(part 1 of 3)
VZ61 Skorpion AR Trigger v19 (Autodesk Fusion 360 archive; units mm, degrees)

design "VZ61 Skorpion AR Trigger" references "KN20 Base"
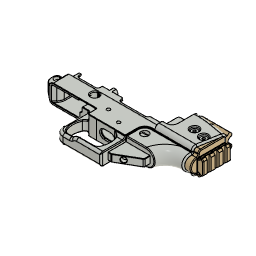
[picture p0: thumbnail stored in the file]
base_feature "Base Feature1"
base_feature "Base Feature1"
base_feature "Base Feature1"
base_feature "Base Feature1"
base_feature "Base Feature1"
base_feature "Base Feature1"
base_feature "Base Feature1"
base_feature "Base Feature1"
base_feature "Base Feature1"
base_feature "Base Feature1"
base_feature "Base Feature1"
base_feature "Base Feature1"
base_feature "Base Feature1"
base_feature "Base Feature1"
base_feature "Base Feature1"
delete_face "DeleteFace1"
sketch "Sketch1" plane through (0, 0, 323.5368) normal (0, 0, 1) x axis (-1, 0, 0)
  line L1 (-298.5983, -1076.3864) -> (-298.5983, -1077.6092)
  line L2 (-296.6171, -1077.6092) -> (-296.6171, -1076.3864)
  line L3 (-258.8669, -1077.8515) -> (-296.6798, -1077.8515)
  line L4 (-258.8669, -1071.9206) -> (-258.8669, -1077.8515)
  line L5 (-257.3965, -1057.333) -> (-257.3965, -1067.8137)
  line L6 (-313.7154, -1057.333) -> (-257.3965, -1057.333)
  line L7 (-315.2154, -1047.0369) -> (-315.2154, -1055.833)
  line L8 (-326.5903, -1045.46) -> (-316.7037, -1045.537)
  line L9 (-363.2907, -1045.46) -> (-326.5903, -1045.46)
  line L10 (-363.7907, -1061.711) -> (-363.7907, -1045.96)
  line L11 (-376.1867, -1071.211) -> (-373.2907, -1071.211)
  line L12 (-376.1867, -1077.8515) -> (-376.1867, -1071.211)
  line L13 (-298.5357, -1077.8515) -> (-376.1867, -1077.8515)
  arc A1 centre (-298.0983, -1077.6092) radius 0.5 clockwise from (-298.5357, -1077.8515) to (-298.5983, -1077.6092)
  arc A2 centre (-299.0983, -1076.3864) radius 0.5 clockwise from (-298.9507, -1075.9087) to (-298.5983, -1076.3864)
  arc A3 centre (-297.6077, -1071.565) radius 4.5466 clockwise from (-298.9507, -1075.9087) to (-296.2648, -1075.9087)
  arc A4 centre (-296.1171, -1076.3864) radius 0.5 clockwise from (-296.6171, -1076.3864) to (-296.2648, -1075.9087)
  arc A5 centre (-297.1171, -1077.6092) radius 0.5 clockwise from (-296.6171, -1077.6092) to (-296.6798, -1077.8515)
  arc A6 centre (-252.3965, -1071.9206) radius 6.4704 clockwise from (-258.8669, -1071.9206) to (-257.3965, -1067.8137)
  arc A7 centre (-313.7154, -1055.833) radius 1.5 clockwise from (-313.7154, -1057.333) to (-315.2154, -1055.833)
  arc A8 centre (-316.7154, -1047.0369) radius 1.5 clockwise from (-316.7037, -1045.537) to (-315.2154, -1047.0369)
  arc A9 centre (-363.2907, -1045.96) radius 0.5 clockwise from (-363.7907, -1045.96) to (-363.2907, -1045.46)
  arc A10 centre (-373.2907, -1061.711) radius 9.5 clockwise from (-363.7907, -1061.711) to (-373.2907, -1071.211)
  circle C1 centre (-323.6435, -1063.6316) radius 2.2185
  circle C2 centre (-345.0557, -1055.656) radius 2.2185
  circle C3 centre (-297.6077, -1071.565) radius 5.125
  concentric A3 C3
  dimension "d1" diameter C3 = 10.25
extrude "Extrude1" cut sketch "Sketch1" profile of L1 A2 A3 A4 L2 C3 against normal blind 23.952
fillet "Fillet1" radius 1
sketch "Sketch2" plane through (0, 0, 312.8688) normal (0, 0, 1) x axis (-1, 0, 0)
  line L1 (-247.0879, -1074.7614) -> (-252.3953, -1074.7614)
  line L2 (-252.3953, -1069.283) -> (-247.0879, -1069.283)
  line L3 (-247.0879, -1075.4614) -> (-252.3953, -1075.4614)
  line L4 (-252.3953, -1068.583) -> (-247.0879, -1068.583)
  line L5 (-252.3965, -1068.583) -> (-247.0879, -1068.583)
  line L6 (-247.0879, -1075.4614) -> (-252.3965, -1075.4614)
  line L7 (-255.8357, -1072.0222) -> (-243.6487, -1072.0222)
  arc A1 centre (-252.3965, -1072.0222) radius 2.7392 clockwise from (-252.3953, -1069.283) to (-252.3953, -1074.7614)
  arc A2 centre (-247.0879, -1072.0222) radius 2.7392 clockwise from (-247.0879, -1069.283) to (-247.0879, -1074.7614)
  arc A3 centre (-252.3965, -1072.0222) radius 2.7392 clockwise from (-252.3965, -1074.7614) to (-252.3965, -1069.283)
  arc A4 centre (-252.3965, -1072.0222) radius 3.4392 clockwise from (-252.3965, -1075.4614) to (-252.3965, -1068.583)
  arc A5 centre (-247.0879, -1072.0222) radius 3.4392 clockwise from (-247.0879, -1068.583) to (-247.0879, -1075.4614)
  circle C1 centre (-252.3965, -1072.0222) radius 3.4392
  arc A6 centre (-252.3965, -1072.0222) radius 3.4392 clockwise from (-252.3965, -1075.4614) to (-252.3965, -1068.583)
  arc A7 centre (-247.0879, -1072.0222) radius 3.4392 clockwise from (-247.0879, -1068.583) to (-247.0879, -1075.4614)
  point P28 (-243.6487, -1072.0222)
  point P29 (-255.8357, -1072.0222)
  point P12 (-252.3965, -1075.4614)
  concentric A3 C1
  tangent L5 A6
  tangent A6 L6
  parallel L5 L6
  tangent L6 A7
  tangent L5 A7
  midpoint A7 P28
  midpoint A6 P29
  midpoint A4 P29
  midpoint A5 P28
  coincident P12 C1
  dimension "d5" = 0.7
  dimension "d6" = 0.7
extrude "Extrude2" cut sketch "Sketch2" profile of A1 L1 A2 L2 A4 L3 A5 L4 C1 along normal blind 7.5
extrude "Extrude3" cut sketch "Sketch2" profile of A1 L1 L2 A4 C1 against normal blind 13
work_plane "WorkPlane1"
fillet "Fillet2" radius 23
fillet "Fillet3" radius 0.5
extrude "Extrude4" cut sketch "Sketch2" profile of L1 A2 L2 A4 L3 A5 L4 C1 L5 A6 L6 A7 along normal blind 12.5
delete_face "DeleteFace2"
delete_face "DeleteFace3"
delete_face "DeleteFace4"
delete_face "DeleteFace5"
delete_face "DeleteFace6"
delete_face "DeleteFace7"
extrude "Extrude5" add of existing geometry blind 0.75
delete_face "DeleteFace8"
delete_face "DeleteFace9"
delete_face "DeleteFace10"
sketch "Sketch3" plane through (0, 0, 323.5368) normal (0, 0, 1) x axis (-1, 0, 0)
  line L1 (-258.8669, -1077.8515) -> (-296.6798, -1077.8515)
  line L2 (-258.8669, -1071.9206) -> (-258.8669, -1077.8515)
  line L3 (-257.3965, -1057.333) -> (-257.3965, -1067.8137)
  line L4 (-313.7154, -1057.333) -> (-257.3965, -1057.333)
  line L5 (-315.2154, -1047.0369) -> (-315.2154, -1055.833)
  line L6 (-326.5903, -1045.46) -> (-316.7037, -1045.537)
  line L7 (-363.2907, -1045.46) -> (-326.5903, -1045.46)
  line L8 (-363.7907, -1061.711) -> (-363.7907, -1045.96)
  line L9 (-376.1867, -1071.211) -> (-373.2907, -1071.211)
  line L10 (-376.1867, -1077.8515) -> (-376.1867, -1071.211)
  line L11 (-298.5357, -1077.8515) -> (-376.1867, -1077.8515)
  circle C1 centre (-345.0557, -1055.656) radius 2
  arc A1 centre (-297.6077, -1071.565) radius 6.125 clockwise from (-298.5983, -1077.6093) to (-296.6171, -1077.6093)
  arc A2 centre (-297.1171, -1077.6092) radius 0.5 clockwise from (-296.6171, -1077.6093) to (-296.6798, -1077.8515)
  arc A3 centre (-252.3965, -1071.9206) radius 6.4704 clockwise from (-258.8669, -1071.9206) to (-257.3965, -1067.8137)
  arc A4 centre (-313.7154, -1055.833) radius 1.5 clockwise from (-313.7154, -1057.333) to (-315.2154, -1055.833)
  arc A5 centre (-316.7154, -1047.0369) radius 1.5 clockwise from (-316.7037, -1045.537) to (-315.2154, -1047.0369)
  arc A6 centre (-363.2907, -1045.96) radius 0.5 clockwise from (-363.7907, -1045.96) to (-363.2907, -1045.46)
  arc A7 centre (-373.2907, -1061.711) radius 9.5 clockwise from (-363.7907, -1061.711) to (-373.2907, -1071.211)
  arc A8 centre (-298.0983, -1077.6092) radius 0.5 clockwise from (-298.5357, -1077.8515) to (-298.5983, -1077.6093)
  circle C2 centre (-323.6435, -1063.6316) radius 2
  circle C3 centre (-345.0557, -1055.656) radius 2.175
  circle C4 centre (-323.6435, -1063.6316) radius 2.175
  concentric C1 C3
  concentric C2 C4
  dimension "d17" diameter C3 = 4.35
  dimension "d18" diameter C4 = 4.35
extrude "Extrude6" cut sketch "Sketch3" profile of C1 C2 C3 C4 against normal blind 51
delete_face "DeleteFace11"
sketch "Sketch4" plane through (201.4676, -35.5242, 0) normal (0.9848, -0.1736, 0) x axis (0.1736, 0.9848, 0)
  circle C1 centre (1146.6543, 311.0803) radius 13
  circle C2 centre (1146.6543, 311.0803) radius 13.75
  dimension "d21" = 0.75
extrude "Extrude7" cut sketch "Sketch4" along normal blind 80
fillet "Fillet4" radius 1 1
sketch "Sketch5" plane through (0, 0, 323.5368) normal (0, 0, 1) x axis (-1, 0, 0)
  line L1 (-258.8669, -1077.8515) -> (-296.6798, -1077.8515)
  line L2 (-258.8669, -1071.9206) -> (-258.8669, -1077.8515)
  line L3 (-257.3965, -1057.333) -> (-257.3965, -1067.8137)
  line L4 (-313.7154, -1057.333) -> (-257.3965, -1057.333)
  line L5 (-315.2154, -1047.0369) -> (-315.2154, -1055.833)
  line L6 (-326.5903, -1045.46) -> (-316.7037, -1045.537)
  line L7 (-363.2907, -1045.46) -> (-326.5903, -1045.46)
  line L8 (-363.7907, -1061.711) -> (-363.7907, -1045.96)
  line L9 (-376.1867, -1071.211) -> (-373.2907, -1071.211)
  line L10 (-376.1867, -1077.8515) -> (-376.1867, -1071.211)
  line L11 (-298.5357, -1077.8515) -> (-376.1867, -1077.8515)
  circle C1 centre (-345.0557, -1055.656) radius 2.175
  circle C2 centre (-323.6435, -1063.6316) radius 2.175
  arc A1 centre (-297.6077, -1071.565) radius 6.125 clockwise from (-298.5983, -1077.6093) to (-296.6171, -1077.6093)
  arc A2 centre (-297.1171, -1077.6092) radius 0.5 clockwise from (-296.6171, -1077.6093) to (-296.6798, -1077.8515)
  arc A3 centre (-252.3965, -1071.9206) radius 6.4704 clockwise from (-258.8669, -1071.9206) to (-257.3965, -1067.8137)
  arc A4 centre (-313.7154, -1055.833) radius 1.5 clockwise from (-313.7154, -1057.333) to (-315.2154, -1055.833)
  arc A5 centre (-316.7154, -1047.0369) radius 1.5 clockwise from (-316.7037, -1045.537) to (-315.2154, -1047.0369)
  arc A6 centre (-363.2907, -1045.96) radius 0.5 clockwise from (-363.7907, -1045.96) to (-363.2907, -1045.46)
  arc A7 centre (-373.2907, -1061.711) radius 9.5 clockwise from (-363.7907, -1061.711) to (-373.2907, -1071.211)
  arc A8 centre (-298.0983, -1077.6092) radius 0.5 clockwise from (-298.5357, -1077.8515) to (-298.5983, -1077.6093)
  circle C3 centre (-345.0557, -1055.656) radius 5
  circle C4 centre (-323.6435, -1063.6316) radius 5
  concentric C1 C3
  concentric C2 C4
  dimension "d26" diameter C3 = 10
  dimension "d27" diameter C4 = 10
extrude "Extrude8" add sketch "Sketch5" profile of C1 C2 C3 C4 along normal blind 2
extrude "Extrude9" add sketch "Sketch5" profile of C1 C2 C3 C4 blind -2 from offset -24.913
fillet "Fillet5" radius 1
external_derived "ExternalDerived1"
ground "Ground1"
align "Align1"
extrude "Extrude1" cut of existing geometry blind -1.5
align "Align2"
extrude "Extrude2" cut of existing geometry blind -128.829
extrude "Extrude3" add of existing geometry blind 8
split "Split1" bodies "Picatinny Base (1)", "Picatinny Base (2)", "Picatinny Base (3)"
sketch "Sketch6" plane through (427.1656, 0, 0) normal (1, 0, 0) x axis (0, 1, 0)
  line L1 (1110.3464, 303.2444) -> (1110.3464, 318.9162)
  line L2 (1116.316, 303.2444) -> (1110.3464, 303.2444)
  line L3 (1119.2278, 300.4758) -> (1116.316, 303.2444)
  line L4 (1122.1477, 303.2444) -> (1119.2278, 300.4758)
  line L5 (1122.1477, 318.9162) -> (1122.1477, 303.2444)
  line L6 (1119.2585, 321.6848) -> (1122.1477, 318.9162)
  line L7 (1116.3613, 318.9162) -> (1119.2585, 321.6848)
  line L8 (1110.3464, 318.9162) -> (1116.3613, 318.9162)
  circle C1 centre (1122.1477, 311.0803) radius 5
  point P10 (1122.1477, 311.0803)
  midpoint L5 P10
  dimension "d40" diameter C1 = 10
extrude "Extrude4" cut sketch "Sketch6" profile of L5 C1 against normal blind 50
copy_paste_bodies "CutPasteBodies1"
sketch "Sketch7" plane through (0, 1046.071, 0) normal (0, -1, 0) x axis (1, 0, 0)
  curve K1 (390.5086, 301.0303) -> (390.5086, 321.1303)
  line L1 (364.7827, 321.1303) -> (390.5086, 321.1303)
  curve K2 (364.7827, 321.1303) -> (364.7907, 320.7332)
  line L2 (364.7907, 315.8553) -> (364.7907, 320.7332)
  line L3 (395.5407, 315.8553) -> (364.7907, 315.8553)
  line L4 (396.0407, 315.3553) -> (395.5407, 315.8553)
  line L5 (396.0407, 306.8053) -> (396.0407, 315.3553)
  line L6 (395.5407, 306.3053) -> (396.0407, 306.8053)
  line L7 (364.7907, 306.3053) -> (395.5407, 306.3053)
  line L8 (364.7907, 301.4275) -> (364.7907, 306.3053)
  curve K3 (364.7907, 301.4275) -> (364.7827, 301.0303)
  line L9 (390.5086, 301.0303) -> (364.7827, 301.0303)
  circle C1 centre (373.6312, 303.5803) radius 1.54
  circle C2 centre (373.6312, 303.5803) radius 2
  concentric C1 C2
  dimension "d43" diameter C2 = 4
extrude "Extrude10" cut sketch "Sketch7" profile of C1 C2 against normal blind 14.5
copy_paste "CopyPaste1"
work_plane "WorkPlane2" AlongDistance 0
split "Split1" bodies "AR-15 Buffer Tube"
derived_base_feature "Derived Base Feature2" bodies "Picatinny Base (1)"
work_plane "WorkPlane1" RotateAngle 90
sketch "Sketch1" plane through (29, 0, -19) normal (0.9848, 0, -0.1736) x axis (0, -1, 0)
  line L1 (-15.7419, -31.5631) -> (-15.7419, -2.9544)
  line L2 (-11.5035, -34.8481) -> (-12.4569, -34.8481)
  curve K1 (-11.5035, -34.8481) -> (-9.0091, -37.1129)
  curve K2 (-9.0091, -37.1129) -> (9.0091, -37.1129)
  curve K3 (9.0091, -37.1129) -> (11.5035, -34.8481)
  line L3 (12.4569, -34.8481) -> (11.5035, -34.8481)
  line L4 (15.7419, -2.9544) -> (15.7419, -31.5631)
  line L5 (-12.7419, 0) -> (12.7419, 0)
  closed curve K4 centre (-12.7419, -2.9544)
  arc A1 centre (-12.4569, -31.5631) radius 3.285 clockwise from (-12.4569, -34.8481) to (-15.7419, -31.5631)
  arc A2 centre (12.4569, -31.5631) radius 3.285 clockwise from (15.7419, -31.5631) to (12.4569, -34.8481)
  closed curve K5 centre (12.7419, -2.9544)
  closed curve K6 centre (0, -18.7113)
extrude "Extrude1" add sketch "Sketch1" along a picked direction blind -13
split "Split2"
copy_paste_bodies "CutPasteBodies1"
align "Align1"
extrude "Extrude2" cut of existing geometry blind -1.5
align "Align2"
extrude "Extrude3" cut of existing geometry blind -128.829
component_from_bodies "Body->Comp1"
copy_paste "CopyPaste1"
position "Position1"
extrude "Extrude1" add of existing geometry blind 3
split "Split1" bodies "90 (1)", "90 (2)"
fillet "Fillet1" radius 1
copy_paste_bodies "CopyPasteBodies1"
copy_paste_bodies "CutPasteBodies2"
extrude "Extrude4" cut of existing geometry blind 12.5
split "Split3" bodies "Angled Plate"
sketch "Sketch2" plane through (29, 0, 0) normal (1, 0, 0) x axis (0, 1, 0)
  line L1 (15.7419, 13.05) -> (15.7419, -16)
  line L2 (11.5035, 16.3857) -> (12.4569, 16.3857)
  curve K1 (11.5035, 16.3857) -> (9.0091, 18.6855)
  curve K2 (9.0091, 18.6855) -> (-9.0091, 18.6855)
  curve K3 (-9.0091, 18.6855) -> (-11.5035, 16.3857)
  line L3 (-12.4569, 16.3857) -> (-11.5035, 16.3857)
  line L4 (-15.7419, -16) -> (-15.7419, 13.05)
  line L5 (12.7419, -19) -> (-12.7419, -19)
  arc A1 centre (12.7419, -16) radius 3 clockwise from (15.7419, -16) to (12.7419, -19)
  closed curve K4 centre (12.4569, 13.05)
  closed curve K5 centre (-12.4569, 13.05)
  arc A2 centre (-12.7419, -16) radius 3 clockwise from (-12.7419, -19) to (-15.7419, -16)
  circle C1 centre (0, 0) radius 14.75
extrude "Extrude5" add sketch "Sketch2" along a picked direction blind 2
derived_base_feature "Derived Base Feature3" bodies "Picatinny Base (2)", "Picatinny Base (1)"
copy_paste_bodies "CutPasteBodies3"
align "Align3"
extrude "Extrude6" cut of existing geometry blind -128.829
extrude "Extrude7" cut of existing geometry blind -1.5
align "Align4"
split "Split4" bodies "Non-Angled"
copy_paste_bodies "CutPasteBodies1"
combine "Combine1" bodies "Picatinny Base (1) (1)"
component_from_bodies "Body->Comp2"
copy_paste "CutPaste"
copy_paste_bodies "CopyPasteBodies1"
combine "Combine1"
delete_face "DeleteFace1"
extrude "Extrude11" cut of existing geometry blind -68
fillet "Fillet1" radius 1
fillet "Fillet2" radius 0.5
fillet "Fillet1" radius 1
fillet "Fillet2" radius 1
sketch "Sketch3" plane through (29, 0, 0) normal (-1, 0, 0) x axis (0, -1, 0)
  line L1 (11.5035, 16.3857) -> (12.4569, 16.3857)
  curve K1 (9.0091, 18.6855) -> (11.5035, 16.3857)
  curve K2 (-9.0091, 18.6855) -> (9.0091, 18.6855)
  curve K3 (-11.5035, 16.3857) -> (-9.0091, 18.6855)
  line L2 (-12.4569, 16.3857) -> (-11.5035, 16.3857)
  line L3 (-15.7419, -16) -> (-15.7419, 13.05)
  line L4 (12.7419, -19) -> (-12.7419, -19)
  line L5 (15.7419, 13.05) -> (15.7419, -16)
  closed curve K4 centre (-12.4569, 13.05)
  arc A1 centre (-12.7419, -16) radius 3 clockwise from (-12.7419, -19) to (-15.7419, -16)
  arc A2 centre (12.7419, -16) radius 3 clockwise from (15.7419, -16) to (12.7419, -19)
  closed curve K5 centre (12.4569, 13.05)
  circle C1 centre (0, 0) radius 13.5
extrude "Extrude9" cut sketch "Sketch3" along a picked direction blind 95
delete_face "DeleteFace1"
delete_face "DeleteFace2"
delete_face "DeleteFace3"
delete_face "DeleteFace4"
chamfer "Chamfer1" distance 1.5
chamfer "Chamfer2" distance 1.5
component_from_bodies "Body->Comp3"
offset_faces "OffsetFaces1" distance 0.25
delete_face "DeleteFace12"
sketch "Sketch8" plane through (0, 0, 317.0598) normal (0, 0, 1) x axis (-1, 0, 0)
  line L1 (-247.0879, -1068.583) -> (-252.3953, -1068.583)
  line L2 (-252.3953, -1075.4614) -> (-247.0879, -1075.4614)
  line L3 (-256.8669, -1076.0942) -> (-256.8669, -1071.9206)
  line L4 (-247.6213, -1076.0942) -> (-256.8669, -1076.0942)
  line L5 (-243.5493, -1068.9541) -> (-243.5493, -1072.0222)
  line L6 (-250.416, -1058.9901) -> (-247.2509, -1061.4289)
  line L7 (-250.416, -1067.9128) -> (-250.416, -1058.9901)
  line L8 (-252.3965, -1067.4502) -> (-252.3965, -1071.9206)
  line L9 (-244, -1067.4502) -> (-252.3965, -1067.4502)
  line L10 (-244, -1070.5078) -> (-244, -1067.4502)
  line L11 (-256.8669, -1068.8387) -> (-256.8669, -1071.9206)
  line L12 (-246.0217, -1070.9571) -> (-254.8888, -1070.8604)
  line L13 (-254.8452, -1066.8606) -> (-245.9781, -1066.9573)
  line L14 (-244, -1068.979) -> (-256.8669, -1068.8387)
  arc A1 centre (-247.0879, -1072.0222) radius 3.4392 clockwise from (-247.0879, -1068.583) to (-247.0879, -1075.4614)
  arc A2 centre (-252.3965, -1072.0222) radius 3.4392 clockwise from (-252.3953, -1075.4614) to (-252.3953, -1068.583)
  arc A3 centre (-252.3965, -1071.9206) radius 4.4704 clockwise from (-256.8669, -1071.9206) to (-250.416, -1067.9128)
  arc A4 centre (-247.6213, -1072.0222) radius 4.072 clockwise from (-243.5493, -1072.0222) to (-247.6213, -1076.0942)
  arc A5 centre (-253.0493, -1068.9541) radius 9.5 clockwise from (-247.2509, -1061.4289) to (-243.5493, -1068.9541)
  circle C1 centre (-252.3965, -1071.9206) radius 4.4704
  arc A6 centre (-245.9999, -1068.9572) radius 2 clockwise from (-245.9781, -1066.9573) to (-246.0217, -1070.9571)
  arc A7 centre (-254.867, -1068.8605) radius 2 clockwise from (-254.8888, -1070.8604) to (-254.8452, -1066.8606)
  point P10 (-252.3965, -1071.9206)
  point P20 (-252.3965, -1071.9206)
  point P21 (-252.3965, -1067.4502)
  point P23 (-244, -1070.5078)
  point P9 (-256.8669, -1071.9206)
  point P24 (-256.8669, -1071.9206)
  point P25 (-256.8669, -1068.8387)
  point P32 (-244, -1068.979)
  concentric A3 C1
  vertical L8
  coincident P10 P20
  coincident A3 P21
  coincident C1 P21
  tangent A3 L9
  coincident A1 P23
  perpendicular L9 L10
  coincident P9 P24
  tangent A3 L11
  tangent L12 A6
  tangent A6 L13
  parallel L12 L13
  tangent L13 A7
  tangent L12 A7
  midpoint P25 A7
  midpoint A6 P32
  midpoint L10 P32
  dimension "d81" diameter A6 = 4
extrude "Extrude12" cut sketch "Sketch8" profile of A3 L7 C1 L9 L11 L13 A7 along normal blind 42
extrude "Extrude13" cut of existing geometry blind -15 from offset -11.959
sketch "Sketch9" plane through (0, 0, 305.1008) normal (0, 0, -1) x axis (1, 0, 0)
  line L1 (250.416, -1058.9901) -> (250.416, -1066.9089)
  line L2 (247.2509, -1061.4289) -> (250.416, -1058.9901)
  line L3 (243.5493, -1072.0222) -> (243.5493, -1068.9541)
  line L4 (256.8669, -1076.0942) -> (247.6213, -1076.0942)
  line L5 (256.8669, -1071.9206) -> (256.8669, -1076.0942)
  line L6 (256.8669, -1068.8387) -> (256.8669, -1071.9206)
  line L7 (250.416, -1066.9089) -> (254.8452, -1066.8606)
  line L8 (252.3965, -1071.0222) -> (252.3965, -1072.0222)
  arc A1 centre (253.0493, -1068.9541) radius 9.5 clockwise from (243.5493, -1068.9541) to (247.2509, -1061.4289)
  arc A2 centre (247.6213, -1072.0222) radius 4.072 clockwise from (247.6213, -1076.0942) to (243.5493, -1072.0222)
  arc A3 centre (254.867, -1068.8605) radius 2 clockwise from (254.8452, -1066.8606) to (256.8669, -1068.8387)
  arc A4 centre (252.3965, -1072.0222) radius 3.4392 clockwise from (252.3953, -1075.4614) to (252.3953, -1068.583)
  arc A5 centre (252.3965, -1072.0222) radius 3.4392 clockwise from (252.3953, -1068.583) to (252.3953, -1075.4614)
  circle C1 centre (252.3965, -1071.0222) radius 3.375
  point P17 (252.3965, -1072.0222)
  point P18 (252.3965, -1072.0222)
  point P19 (252.3965, -1071.0222)
  point P20 (252.3965, -1071.0222)
  coincident P17 P18
  vertical L8
  coincident P19 P20
  dimension "d85" distance P18 P19 = 1
  dimension "d86" diameter C1 = 6.75
extrude "Extrude14" cut sketch "Sketch9" profile of A4 A5 C1 against normal blind 11.959
extrude "Extrude15" add sketch "Sketch9" profile of A4 A5 C1 against normal blind 11.959
delete_face "DeleteFace13"
extrude "Extrude16" cut sketch "Sketch9" profile of A4 A5 C1 against normal blind 33
delete_face "DeleteFace14"
sketch "Sketch10" plane through (0, 0, 317.0598) normal (0, 0, 1) x axis (-1, 0, 0)
  line L1 (-256.8669, -1076.0942) -> (-256.8669, -1068.8387)
  line L2 (-247.6213, -1076.0942) -> (-256.8669, -1076.0942)
  line L3 (-243.5493, -1068.9541) -> (-243.5493, -1072.0222)
  line L4 (-250.416, -1058.9901) -> (-247.2509, -1061.4289)
  line L5 (-250.416, -1066.9089) -> (-250.416, -1058.9901)
  line L6 (-254.8452, -1066.8606) -> (-250.416, -1066.9089)
  line L7 (-255.7715, -1071.0222) -> (-252.3965, -1071.0222)
  line L8 (-249.1465, -1074.3972) -> (-252.3965, -1074.3972)
  line L9 (-252.3965, -1067.6472) -> (-249.1465, -1067.6472)
  line L10 (-245.7715, -1071.0222) -> (-255.7715, -1071.0222)
  arc A1 centre (-247.6213, -1072.0222) radius 4.072 clockwise from (-243.5493, -1072.0222) to (-247.6213, -1076.0942)
  arc A2 centre (-253.0493, -1068.9541) radius 9.5 clockwise from (-247.2509, -1061.4289) to (-243.5493, -1068.9541)
  arc A3 centre (-254.867, -1068.8605) radius 2 clockwise from (-256.8669, -1068.8387) to (-254.8452, -1066.8606)
  circle C1 centre (-252.3965, -1071.0222) radius 3.375
  arc A4 centre (-249.1465, -1071.0222) radius 3.375 clockwise from (-249.1465, -1067.6472) to (-249.1465, -1074.3972)
  arc A5 centre (-252.3965, -1071.0222) radius 3.375 clockwise from (-252.3965, -1074.3972) to (-252.3965, -1067.6472)
  circle C2 centre (-252.3965, -1071.0222) radius 3.375
  point P14 (-252.3965, -1071.0222)
  point P15 (-252.3965, -1071.0222)
  point P16 (-255.7715, -1071.0222)
  point P23 (-245.7715, -1071.0222)
  coincident P14 P15
  coincident C1 P16
  horizontal L7
  tangent L8 A4
  tangent A4 L9
  parallel L8 L9
  tangent L9 A5
  tangent L8 A5
  midpoint P16 A5
  midpoint A4 P23
  parallel L7 L10
  tangent L9 C2
  dimension "d93" distance P16 P23 = 10
fillet "Fillet6" radius 2.5
delete_face "DeleteFace15"
sketch "Sketch11" plane through (0, 0, 317.0598) normal (0, 0, 1) x axis (-1, 0, 0)
  line L1 (-256.8669, -1076.0942) -> (-256.8669, -1068.8387)
  line L2 (-247.6213, -1076.0942) -> (-256.8669, -1076.0942)
  line L3 (-243.5493, -1068.9541) -> (-243.5493, -1072.0222)
  line L4 (-250.416, -1058.9901) -> (-247.2509, -1061.4289)
  line L5 (-250.416, -1064.4088) -> (-250.416, -1058.9901)
  curve K1 (-254.4744, -1066.8647) -> (-250.416, -1064.4088)
  line L6 (-254.8452, -1066.8606) -> (-254.4744, -1066.8647)
  line L7 (-248.4133, -1074.664) -> (-252.1296, -1074.664)
  line L8 (-252.1296, -1067.3803) -> (-248.4133, -1067.3803)
  line L9 (-244.7715, -1071.0222) -> (-255.7715, -1071.0222)
  arc A1 centre (-247.6213, -1072.0222) radius 4.072 clockwise from (-243.5493, -1072.0222) to (-247.6213, -1076.0942)
  arc A2 centre (-253.0493, -1068.9541) radius 9.5 clockwise from (-247.2509, -1061.4289) to (-243.5493, -1068.9541)
  arc A3 centre (-254.867, -1068.8605) radius 2 clockwise from (-256.8669, -1068.8387) to (-254.8452, -1066.8606)
  circle C1 centre (-252.3965, -1071.0222) radius 3.375
  arc A4 centre (-248.4133, -1071.0222) radius 3.6418 clockwise from (-248.4133, -1067.3803) to (-248.4133, -1074.664)
  arc A5 centre (-252.1296, -1071.0222) radius 3.6418 clockwise from (-252.1296, -1074.664) to (-252.1296, -1067.3803)
  point P22 (-255.7715, -1071.0222)
  point P23 (-244.7715, -1071.0222)
  tangent L7 A4
  tangent A4 L8
  parallel L7 L8
  tangent L8 A5
  tangent L7 A5
  midpoint A5 P22
  midpoint A4 P23
  horizontal L9
  coincident C1 P22
  dimension "d95" distance P22 P23 = 11
extrude "Extrude17" cut sketch "Sketch11" profile of C1 L7 A4 L8 A5 against normal blind 4.5
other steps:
derived_base_feature "Derived Base Feature1" bodies "Picatinny Base"
base_feature "Base Feature1" bodies "90"
base_feature "Base Feature1" bodies "Picatinny Base (1) (1)", "Non-Angled"
base_feature "Base Feature1" bodies "Angled Plate"
base_feature "Base Feature1" bodies "AR-15 Buffer Tube"
base_feature "Base Feature2" bodies "Angled Plate (1)"
base_feature "Base Feature2" bodies "Picatinny Base (1)", "90"
base_feature "Base Feature3" bodies "Nub"
base_feature "Base Feature4" bodies "Picatinny Base (1) (1)"
base_feature "Base Feature1"
extrude "Extrude8" cut of existing geometry blind -68
base_feature "Base Feature2" bodies "Picatinny Base (1)"
create_component "CreateComponent1"
create_component "CreateComponent2"
create_component "CreateComponent1"
create_component "CreateComponent1"
create_component "CreateComponent1"
create_component "CreateComponent1"
create_component "CreateComponent2"
create_component "CreateComponent3"
create_component "CreateComponent4"
create_component "CreateComponent2"
create_component "CreateComponent1"
create_component "CreateComponent2"
create_component "CreateComponent3"
create_component "CreateComponent4"
create_component "CreateComponent5"
create_component "CreateComponent3"
create_component "CreateComponent1"
create_component "CreateComponent2"
create_component "CreateComponent3"
create_component "CreateComponent3"
create_component "CreateComponent4"
remove_body "RemoveBody1"
remove_body "RemoveBody2"
create_component "CreateComponent1"
remove_body "RemoveBody1"
remove_body "RemoveBody3"
remove_body "RemoveBody4"
create_component "CreateComponent2"
remove_body "RemoveBody2"
remove_body "RemoveBody3"
create_component "CreateComponent3"
remove_body "RemoveBody4"
remove_instance "RemoveInstance1"
remove_body "RemoveBody1"
create_component "CreateComponent4"
remove_body "RemoveBody5"
named bodies: "Picatinny Base", "Picatinny Base (1)", "Picatinny Base (2)", "Picatinny Base (3)", "AR-15 Buffer Tube", "90", "90 (1)", "90 (2)", "Nub", "Angled Plate", "Picatinny Base (1) (1)", "Non-Angled", "Angled Plate (1)"

design "HRR Blast Shield"
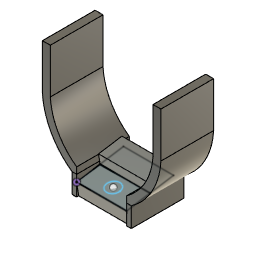
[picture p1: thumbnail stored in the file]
work_plane "WorkPlane1" RotateAngle 9
sketch "Base" plane through (12.125, 0, 0) normal (0, -0.1564, 0.9877) x axis (1, 0, 0)
  line L1 (19, 0) -> (0, 0)
  line L2 (19, 9) -> (19, 0)
  line L3 (0, 9) -> (19, 9)
  line L4 (0, 0) -> (0, 9)
  line L5 (19, 9) -> (0, 9)
  line L6 (19, 18) -> (19, 9)
  line L7 (0, 18) -> (19, 18)
  line L8 (0, 9) -> (0, 18)
  circle C1 centre (9.4705, 4.5) radius 2.5
  point P1 (0, 0)
  point P2 (0, 0)
  point P3 (19, 0)
  point P5 (0, 9)
  point P7 (19, 9)
  point P9 (0, 18)
  horizontal L1
  vertical L2
  horizontal L3
  vertical L4
  coincident P1 P2
  horizontal L5
  vertical L6
  horizontal L7
  vertical L8
  dimension "d2" distance P2 P3 = 19
  dimension "d3" distance P2 P5 = 9
  dimension "d4" diameter C1 = 5
  dimension "d5" distance P5 P7 = 19
  dimension "d6" distance P5 P9 = 9
extrude "Extrude1" new body sketch "Base" against normal blind 5
extrude "Extrude2" add sketch "Base" profile of L3 L5 L6 L7 L8 along normal blind 3.75
work_plane "WorkPlane2" AlongDistance 5.3
sketch "Blast Shield" plane through (0, 0, 0) normal (0, 1, 0) x axis (1, 0, 0)
  line L1 (2.125, -40) -> (2.125, -23)
  line L2 (-0.875, -40) -> (-0.875, -22.9143)
  line L3 (2.125, -40) -> (-0.875, -40)
  line L4 (12.125, -2.5505) -> (10.3929, -2.5505)
  line L5 (12.125, -5) -> (12.125, -2.5505)
  line L6 (12.125, -5.1117) -> (12.125, -1.4079)
  line L7 (21.625, -5.1117) -> (21.625, -23.1117)
  line L8 (31.125, -5.1117) -> (12.125, -5.1117)
  line L9 (44.125, -40) -> (44.125, -22.9143)
  line L10 (31.125, -5) -> (31.125, -2.5505)
  line L11 (41.125, -40) -> (41.125, -23)
  line L12 (31.125, -2.5505) -> (32.8571, -2.5505)
  line L13 (41.125, -40) -> (44.125, -40)
  circle C1 centre (21.625, -23.1117) radius 18
  arc A1 centre (25.842, -24.3983) radius 23.7582 clockwise from (2.125, -23) to (12.125, -5)
  arc A2 centre (25.842, -24.3983) radius 26.7582 clockwise from (-0.875, -22.9143) to (10.3929, -2.5505)
  arc A3 centre (17.408, -24.3983) radius 23.7582 clockwise from (31.125, -5) to (41.125, -23)
  arc A4 centre (17.408, -24.3983) radius 26.7582 clockwise from (32.8571, -2.5505) to (44.125, -22.9143)
  point P2 (21.625, -23.1117)
  point P14 (21.625, -23.1117)
  point P15 (21.625, -5.1117)
  point P3 (12.125, -5)
  point P17 (31.125, -5)
  point P4 (2.125, -23)
  point P22 (41.125, -23)
  point P6 (2.125, -40)
  point P19 (41.125, -40)
  point P8 (-0.875, -22.9143)
  point P24 (44.125, -22.9143)
  point P9 (10.3929, -2.5505)
  point P23 (32.8571, -2.5505)
  point P10 (-0.875, -40)
  point P21 (44.125, -40)
  point P11 (12.125, -2.5505)
  point P20 (31.125, -2.5505)
  point P13 (12.125, -5.1117)
  point P18 (31.125, -5.1117)
  vertical L1
  perpendicular L1 L3
  perpendicular L2 L4
  perpendicular L4 L5
  collinear L5 L6
  coincident P2 P14
  coincident C1 P15
  vertical L7
  coincident P15 L8
  midpoint P15 L8
  symmetric P3 L7 P17
  symmetric P4 L7 P22
  symmetric A1 L7 A3
  symmetric P6 L7 P19
  symmetric P8 L7 P24
  symmetric P9 L7 P23
  symmetric A2 L7 A4
  symmetric P10 L7 P21
  symmetric P11 L7 P20
  symmetric P13 L7 P18
  dimension "d16" diameter C1 = 36
  dimension "d17" = 3
extrude "Extrude4" add sketch "Blast Shield" profile of A1 L1 A2 L2 L3 L4 L5 L6 L9 L10 A3 L11 A4 L12 L13 along normal blind 20
extrude "Extrude5" new body of existing geometry blind 7.489

design "Heritage Rough Rider - Cylinder Rod"
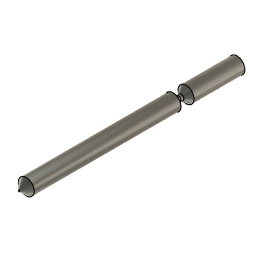
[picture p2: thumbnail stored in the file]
sketch "Sketch1" plane through (0, 0, 0) normal (0, 1, 0) x axis (1, 0, 0)
  circle C1 centre (0, 0) radius 2.75
  point P1 (0, 0)
  point P2 (0, 0)
  coincident P1 P2
  dimension "d1" diameter C1 = 5.5
extrude "Extrude1" new body sketch "Sketch1" along normal blind 75
chamfer "Chamfer1" distance 2.5
work_plane "WorkPlane1" AlongDistance 53
work_plane "WorkPlane2" AlongDistance 4.5
split "Split1"
work_plane "WorkPlane3" AlongDistance 1.75
work_plane "WorkPlane4" AlongDistance -1.75
split "Split2"
offset_faces "OffsetFaces1" distance -1.8
chamfer "Chamfer2" distance 1.75

design "HRR PRA Base" references "HRR Blast Shield", "Heritage Rough Rider - Cylinder Rod"
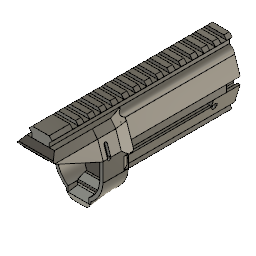
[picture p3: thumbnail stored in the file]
external_derived "ExternalDerived1" bodies "Body3", "Body4"
work_plane "WorkPlane1" AlongDistance -10
split "Split1"
sketch "Sketch1" plane through (0, 0, 0) normal (0, 1, 0) x axis (1, 0, 0)
  line L1 (2.794, -10.16) -> (2.794, 0)
  line L2 (5.794, -0.254) -> (5.794, -10.16)
  line L3 (11.176, 3.0514) -> (-0.0149, 3.0514)
  line L4 (-12.7, -25.4) -> (-12.7, -7.62)
  line L5 (12.7, -25.4) -> (-12.7, -25.4)
  line L6 (12.7, -10.16) -> (12.7, -25.4)
  line L7 (-8.3633, -7.6184) -> (-12.7, -7.6184)
  line L8 (-8.3633, -7.6184) -> (12.7, -10.16)
  line L9 (-12.7, -7.6184) -> (-12.7, -7.62)
  line L10 (15.8717, -8.098) -> (12.7, -25.4)
  line L11 (6.6816, -17.7411) -> (14.6433, -9.312)
  circle C1 centre (10.922, -4.318) radius 5.1
  circle C2 centre (-0.0149, 3.0514) radius 5.75
  circle C3 centre (0, -11.43) radius 8.275
  circle C4 centre (0, -11.43) radius 9.1909
  circle C5 centre (10.922, -4.318) radius 6.228
  point P7 (-0.0149, 3.0514)
  point P9 (-0.0149, 3.0514)
  point P17 (-12.7, -7.6184)
  point P18 (-8.3633, -7.6184)
  point P19 (12.7, -10.16)
  point P20 (-8.3633, -7.6184)
  point P21 (-12.7, -7.62)
  point P22 (-12.7, -7.6184)
  point P23 (12.7, -25.4)
  point P24 (15.8717, -8.098)
  point P25 (14.6433, -9.312)
  point P26 (6.6816, -17.7411)
  coincident P7 P9
  coincident L4 P17
  coincident C4 P18
  coincident L6 P19
  coincident L7 P20
  coincident C4 P20
  coincident L4 P21
  coincident L7 P22
  coincident L5 P23
  coincident L6 P23
  coincident C5 P24
  coincident C5 P25
  coincident C4 P26
  tangent C4 L11
extrude "Extrude1" new body sketch "Sketch1" profile of C4 C5 L4 L5 L6 L7 L9 L10 L11 along normal blind 203.2
mesh "Mesh1"
sketch "Sketch2" plane through (-12.7, 0, 0) normal (-1, 0, 0) x axis (0, -1, 0)
  line L1 (-65.024, 25.4) -> (-65.024, 7.6184)
  line L2 (-268.224, 25.4) -> (-65.024, 25.4)
  line L3 (-268.224, 7.6184) -> (-268.224, 25.4)
  line L4 (-65.024, 7.6184) -> (-268.224, 7.6184)
  line L5 (-65.024, 7.6184) -> (-74.9919, 7.6184)
  line L6 (-65.024, -7.543) -> (-65.024, 7.6184)
  line L7 (-74.9919, -7.543) -> (-65.024, -7.543)
  line L8 (-74.9919, 7.6184) -> (-74.9919, -7.543)
  point P6 (-74.9919, 7.6184)
  horizontal L5
  vertical L6
  horizontal L7
  vertical L8
  coincident L4 P6
extrude "Extrude2" add sketch "Sketch2" profile of L4 L5 L6 L7 L8 against normal blind 15.24
extrude "Extrude3" cut sketch "Sketch1" profile of L1 C2 C3 C4 L8 along normal blind 35.56 bodies "Body2 (1) (3)"
work_plane "WorkPlane2" sketch "Sketch1" AlongDistance 80
sketch "Sketch3" plane through (0, 65.024, 0) normal (0, 1, 0) x axis (1, 0, 0)
  line L1 (-8.3787, 2.7496) -> (0, 2.7496)
  line L2 (-8.3787, -2.4156) -> (-8.3787, 2.7496)
  line L3 (0, -2.4156) -> (-8.3787, -2.4156)
  line L4 (0, 2.7496) -> (0, -2.4156)
  horizontal L1
  vertical L2
  horizontal L3
  vertical L4
extrude "Extrude4" new body sketch "Sketch3" along normal blind 9.906
sketch "Sketch4" plane through (0, 268.224, 0) normal (0, 1, 0) x axis (-1, 0, 0)
  line L1 (12.7, 25.4) -> (12.7, 7.6184)
  line L2 (-12.7, 25.4) -> (12.7, 25.4)
  line L3 (-15.8717, 8.098) -> (-12.7, 25.4)
  line L4 (-12.7, 11.3694) -> (-12.7, 10.2868)
  line L5 (-6.6816, 17.7411) -> (-12.7, 11.3694)
  line L6 (12.7, 7.6184) -> (8.3633, 7.6184)
  line L7 (10.16, 25.4) -> (-10.922, 25.4)
  line L8 (10.16, -12.7) -> (10.16, 25.4)
  line L9 (-10.922, -12.7) -> (10.16, -12.7)
  line L10 (-10.922, 25.4) -> (-10.922, -12.7)
  arc A1 centre (-10.922, 4.318) radius 6.228 clockwise from (-15.8717, 8.098) to (-12.7, 10.2868)
  arc A2 centre (0, 11.43) radius 9.1909 clockwise from (-6.6816, 17.7411) to (8.3633, 7.6184)
  point P12 (-10.922, 25.4)
  horizontal L7
  vertical L8
  horizontal L9
  vertical L10
  coincident L2 P12
extrude "Extrude5" add sketch "Sketch4" profile of L5 A2 L6 L8 L9 L10 against normal blind 123.19
sketch "Sketch5" plane through (0, 268.224, 0) normal (0, 1, 0) x axis (-1, 0, 0)
  line L1 (12.7, 25.4) -> (12.7, 7.6184)
  line L2 (-12.7, 25.4) -> (12.7, 25.4)
  line L3 (-15.8717, 8.098) -> (-12.7, 25.4)
  line L4 (-12.7, 11.3694) -> (-12.7, 10.2868)
  line L5 (-10.922, 13.2518) -> (-12.7, 11.3694)
  line L6 (-10.922, -12.7) -> (-10.922, 13.2518)
  line L7 (10.16, -12.7) -> (-10.922, -12.7)
  line L8 (10.16, 7.6184) -> (10.16, -12.7)
  line L9 (12.7, 7.6184) -> (10.16, 7.6184)
  line L10 (1.2117, 23.5797) -> (-1.2883, 23.5797)
  line L11 (1.2117, 19.693) -> (1.2117, 23.5797)
  line L12 (-1.2883, 19.693) -> (1.2117, 19.693)
  line L13 (-1.2883, 23.5797) -> (-1.2883, 19.693)
  arc A1 centre (-10.922, 4.318) radius 6.228 clockwise from (-15.8717, 8.098) to (-12.7, 10.2868)
  circle C1 centre (0, 11.43) radius 8.5
  point P14 (-1.2883, 23.5797)
  point P15 (1.2117, 23.5797)
  point P17 (-1.2883, 19.693)
  horizontal L10
  vertical L11
  horizontal L12
  vertical L13
  dimension "d18" distance P14 P15 = 2.5
  dimension "d30" distance P14 P17 = 3.8868 (= "0.074282 in + 2 mm")
  dimension "d31" diameter C1 = 17
extrude "Extrude6" cut sketch "Sketch5" profile of C1 L10 L11 L12 L13 against normal blind 124.46
mesh "Mesh2"
extrude "Extrude7" cut sketch "Sketch1" profile of C1 L2 C3 C4 C5 L6 L8 along normal blind 88.31 (= "3.15 in + 8.3 mm")
sketch "Sketch6" plane through (0, 145.024, 16.5092) normal (0, 1, 0) x axis (1, 0, 0)
  line L1 (17.3873, 8.89) -> (10.922, 8.89)
  line L2 (17.3873, -12.5197) -> (17.3873, 8.89)
  line L3 (10.922, -12.5197) -> (17.3873, -12.5197)
  line L4 (10.922, 8.89) -> (10.922, -12.5197)
  horizontal L1
  vertical L2
  horizontal L3
  vertical L4
extrude "Extrude8" cut sketch "Sketch6" distance 149.86
sketch "Sketch7" plane through (0, 65, 0) normal (0, 1, 0) x axis (1, 0, 0)
  line L1 (2.7494, 2.794) -> (-2.794, 2.794)
  line L2 (2.7494, 0.794) -> (2.7494, 2.794)
  line L3 (-2.794, 0.794) -> (2.7494, 0.794)
  line L4 (-2.794, 2.794) -> (-2.794, 0.794)
extrude "Extrude9" new body of existing geometry blind 4.4958
extrude "Extrude10" cut sketch "Sketch7" against normal blind 4.4958
extrude "Extrude11" cut sketch "Sketch5" profile of C1 L10 L11 L12 L13 against normal blind 210.82
move_face "MoveFace1"
sketch "Sketch11" plane through (1.5859, 268.224, 6.35) normal (0, 1, 0) x axis (-1, 0, 0)
  line L1 (-10.9855, 19.05) -> (14.4145, 19.05)
  line L2 (-10.9855, -19.05) -> (-10.9855, 19.05)
  line L3 (14.4145, -19.05) -> (-10.9855, -19.05)
  line L4 (14.4145, 19.05) -> (14.4145, -19.05)
  point P2 (14.4145, 19.05)
  point P3 (-10.9855, 19.05)
  point P5 (14.4145, -19.05)
  horizontal L1
  vertical L2
  horizontal L3
  vertical L4
  dimension "d34" distance P2 P3 = 25.4
  dimension "d35" distance P2 P5 = 38.1
extrude "Extrude12" add sketch "Sketch11" against normal blind 114.935
extrude "Extrude13" cut sketch "Sketch5" profile of C1 L10 L11 L12 L13 against normal blind 233.68
sketch "Sketch12" plane through (0, 0, 0) normal (0, 1, 0) x axis (1, 0, 0)
  line L1 (12.7, 12.7) -> (0, 12.7)
  line L2 (17.78, -3.81) -> (12.7, 12.7)
  line L3 (17.78, -10.16) -> (17.78, -3.81)
  line L4 (12.7, -25.4) -> (17.78, -10.16)
  line L5 (-12.7, -25.4) -> (12.7, -25.4)
  line L6 (-17.78, -10.16) -> (-12.7, -25.4)
  line L7 (-17.78, -3.81) -> (-17.78, -10.16)
  line L8 (-12.7, 12.7) -> (-17.78, -3.81)
  line L9 (0, 12.7) -> (-12.7, 12.7)
extrude "Extrude14" new body sketch "Sketch12" along normal blind 116.84
extrude "Extrude15" cut sketch "Sketch5" profile of C1 L10 L11 L12 L13 against normal blind 243.84 and along normal blind 20.32
sketch "Sketch13" plane through (0, 0, 0) normal (0, 1, 0) x axis (1, 0, 0)
sketch "Sketch14" plane through (0, 65.024, 0) normal (0, 1, 0) x axis (1, 0, 0)
  line L1 (12.7, 12.7) -> (10.922, 12.7)
  line L2 (17.018, -1.27) -> (12.7, 12.7)
  line L3 (16.3531, -1.27) -> (17.018, -1.27)
  line L4 (10.922, 1.9099) -> (10.922, 12.7)
  line L5 (17.1292, -3.81) -> (17.78, -3.81)
  line L6 (17.78, -10.16) -> (17.78, -3.81)
  line L7 (12.7, -25.4) -> (17.78, -10.16)
  line L8 (10.922, -25.4) -> (12.7, -25.4)
  line L9 (10.922, -10.5459) -> (10.922, -25.4)
  circle C1 centre (10.922, -4.318) radius 6.2279
  point P6 (16.3531, -1.27)
  point P7 (10.922, 1.9099)
  point P9 (17.1292, -3.81)
  point P13 (10.922, -10.5459)
  horizontal L1
  coincident C1 P6
  parallel L1 L3
  coincident C1 P7
  perpendicular L1 L4
  coincident C1 P9
  perpendicular L4 L5
  perpendicular L5 L6
  perpendicular L6 L8
  coincident C1 P13
  perpendicular L8 L9
extrude "Extrude16" add sketch "Sketch14" along normal blind 88.9
extrude "Extrude17" add of existing geometry blind 5.08
extrude "Extrude18" add of existing geometry blind 15.24
extrude "Extrude19" add of existing geometry blind 5.588 bodies "Body2 (1) (3)"
revolve "Revolve1" AlongAngle 360
revolve "Revolve2" AlongAngle 360
sketch "Sketch15" plane through (10.922, 0, 0) normal (-1, 0, 0) x axis (0, -1, 0)
  line L1 (-65.024, -1.955) -> (-74.9919, -1.955)
  line L2 (-65.024, -1.9099) -> (-65.024, -1.955)
  line L3 (-152.4, -1.9099) -> (-65.024, -1.9099)
  line L4 (-152.4, -1.91) -> (-152.4, -1.9099)
  line L5 (-145.034, -1.91) -> (-152.4, -1.91)
  line L6 (-145.034, -12.7) -> (-145.034, -1.91)
  line L7 (-65.024, -12.7) -> (-145.034, -12.7)
  line L8 (-65.024, -12.623) -> (-65.024, -12.7)
  line L9 (-74.9919, -12.623) -> (-65.024, -12.623)
  line L10 (-74.9919, -1.955) -> (-74.9919, -12.623)
  line L11 (-74.7922, 2.9238) -> (-147.7826, 2.9238)
  line L12 (-74.7922, -4.0762) -> (-74.7922, 2.9238)
  line L13 (-147.7826, -4.0762) -> (-74.7922, -4.0762)
  line L14 (-147.7826, 2.9238) -> (-147.7826, -4.0762)
  line L15 (-74.7922, -12.7) -> (-145.034, -12.7)
  line L16 (-74.7922, -4.0762) -> (-74.7922, -12.7)
  line L17 (-145.034, -4.0762) -> (-74.7922, -4.0762)
  line L18 (-145.034, -12.7) -> (-145.034, -4.0762)
  point P8 (-145.034, -12.7)
  point P16 (-145.034, -12.7)
  point P12 (-147.7826, 2.9238)
  point P15 (-147.7826, -4.0762)
  horizontal L11
  vertical L12
  horizontal L13
  vertical L14
  horizontal L15
  vertical L16
  horizontal L17
  vertical L18
  coincident P8 P16
  dimension "d57" distance P12 P15 = 7
extrude "Extrude20" add sketch "Sketch15" profile of L6 L7 L9 L10 L13 L15 L16 L17 L18 along normal blind 23.622
extrude "Extrude21" add of existing geometry blind 7.366
sketch "Sketch16" plane through (0, 145.034, 0) normal (0, -1, 0) x axis (1, 0, 0)
  line L1 (10.922, -4.0762) -> (-12.7, -4.0762)
  line L2 (10.922, -1.91) -> (10.922, -4.0762)
  line L3 (-1.2117, 20.5407) -> (-1.2117, 19.8432)
  line L4 (-12.7, 7.6184) -> (-8.3633, 7.6184)
  line L5 (-12.7, 25.4) -> (-12.7, 7.6184)
  line L6 (-17.78, 10.16) -> (-12.7, 25.4)
  line L7 (-17.78, 3.81) -> (-17.78, 10.16)
  line L8 (-12.7, -12.7) -> (-17.78, 3.81)
  line L9 (-12.7, -4.0762) -> (-12.7, -12.7)
  line L10 (-17.78, 7.6184) -> (-12.7, 7.6184)
  line L11 (-12.7, 25.4) -> (-17.78, 10.16)
  line L12 (-12.7, 7.6184) -> (-17.78, 3.81)
  line L13 (-17.78, 3.81) -> (-17.78, 7.6184)
  line L14 (-15.3535, -4.0762) -> (-12.7, -4.0762)
  line L15 (-12.7, -12.7) -> (-15.3535, -4.0762)
  arc A1 centre (10.922, 4.318) radius 6.228 clockwise from (10.922, -1.91) to (4.6941, 4.3437)
  arc A2 centre (0, 11.43) radius 8.5 clockwise from (4.6941, 4.3437) to (-1.2117, 19.8432)
  arc A3 centre (0, 11.43) radius 9.1909 clockwise from (-8.3633, 7.6184) to (-1.2117, 20.5407)
  point P11 (-12.7, 7.6184)
  point P16 (-12.7, 7.6184)
  point P17 (-17.78, 7.6184)
  point P13 (-17.78, 10.16)
  point P18 (-17.78, 10.16)
  point P12 (-12.7, 25.4)
  point P19 (-12.7, 25.4)
  point P14 (-17.78, 3.81)
  point P20 (-17.78, 3.81)
  point P21 (-12.7, 7.6184)
  point P22 (-17.78, 3.81)
  point P2 (-12.7, -4.0762)
  point P23 (-12.7, -4.0762)
  point P24 (-15.3535, -4.0762)
  point P15 (-12.7, -12.7)
  point P25 (-12.7, -12.7)
  coincident P11 P16
  coincident L7 P17
  perpendicular L7 L10
  coincident P13 P18
  coincident P12 P19
  coincident P14 P20
  coincident P11 P21
  coincident P14 P22
  coincident P2 P23
  coincident L8 P24
  perpendicular L9 L14
  coincident P15 P25
extrude "Extrude22" add sketch "Sketch16" profile of L5 L6 L7 L8 L9 L10 L11 L12 L13 L14 L15 along normal blind 80.01
extrude "Extrude23" cut of existing geometry blind -127
extrude "Extrude24" cut of existing geometry blind -99.06
sketch "Sketch17" plane through (0, 269.24, 0) normal (0, 1, 0) x axis (-1, 0, 0)
  line L1 (-1.2883, 23.5797) -> (-1.2883, 19.8318)
  line L2 (1.2117, 23.5797) -> (-1.2883, 23.5797)
  line L3 (1.2117, 19.8432) -> (1.2117, 23.5797)
  line L4 (17.78, 3.81) -> (12.7, -12.7)
  line L5 (17.78, 10.16) -> (17.78, 3.81)
  line L6 (12.7, 25.4) -> (17.78, 10.16)
  line L7 (-12.7, 25.4) -> (12.7, 25.4)
  line L8 (-17.78, 10.16) -> (-12.7, 25.4)
  line L9 (-17.78, 3.81) -> (-17.78, 10.16)
  line L10 (-12.7, -12.7) -> (-17.78, 3.81)
  line L11 (12.7, -12.7) -> (-12.7, -12.7)
  line L12 (25.4, 38.1) -> (-25.4, 38.1)
  line L13 (25.4, -25.4) -> (25.4, 38.1)
  line L14 (-25.4, -25.4) -> (25.4, -25.4)
  line L15 (-25.4, 38.1) -> (-25.4, -25.4)
  arc A1 centre (0, 11.43) radius 8.5 clockwise from (1.2117, 19.8432) to (-1.2883, 19.8318)
  horizontal L12
  vertical L13
  horizontal L14
  vertical L15
extrude "Extrude25" cut sketch "Sketch17" against normal blind 76.2
sketch "Sketch18" plane through (0, 193.04, 0) normal (0, 1, 0) x axis (-1, 0, 0)
  line L1 (17.78, 3.81) -> (12.8286, -12.2819)
  line L2 (17.78, 10.16) -> (17.78, 3.81)
  line L3 (12.7, 25.4) -> (17.78, 10.16)
  line L4 (-12.7, 25.4) -> (12.7, 25.4)
  line L5 (-17.78, 10.16) -> (-12.7, 25.4)
  line L6 (-17.78, 3.81) -> (-17.78, 10.16)
  line L7 (-12.7, -12.7) -> (-17.78, 3.81)
  line L8 (12.8286, -12.7) -> (-12.7, -12.7)
  line L9 (12.8286, -12.2819) -> (12.8286, -12.7)
  line L10 (-1.2883, 23.5797) -> (-1.2883, 19.8318)
  line L11 (1.2117, 23.5797) -> (-1.2883, 23.5797)
  line L12 (1.2117, 19.8432) -> (1.2117, 23.5797)
  line L13 (7.62, -5.08) -> (-7.62, -5.08)
  line L14 (7.62, -7.62) -> (7.62, -5.08)
  line L15 (-7.62, -7.62) -> (7.62, -7.62)
  line L16 (-7.62, -5.08) -> (-7.62, -7.62)
  line L17 (-10.16, 12.7) -> (-12.7, 12.7)
  line L18 (-10.16, -2.54) -> (-10.16, 12.7)
  line L19 (-12.7, -2.54) -> (-10.16, -2.54)
  line L20 (-12.7, 12.7) -> (-12.7, -2.54)
  line L21 (12.7, 12.7) -> (10.16, 12.7)
  line L22 (12.7, -2.54) -> (12.7, 12.7)
  line L23 (10.16, -2.54) -> (12.7, -2.54)
  line L24 (10.16, 12.7) -> (10.16, -2.54)
  arc A1 centre (0, 11.43) radius 8.5 clockwise from (1.2117, 19.8432) to (-1.2883, 19.8318)
  horizontal L13
  vertical L14
  horizontal L15
  vertical L16
  horizontal L17
  vertical L18
  horizontal L19
  vertical L20
  horizontal L21
  vertical L22
  horizontal L23
  vertical L24
extrude "Extrude26" add sketch "Sketch18" profile of L13 L14 L15 L16 L17 L18 L19 L20 L21 L22 L23 L24 along normal blind 6.35
sketch "Sketch19" plane through (0, 145.034, 0) normal (0, -1, 0) x axis (1, 0, 0)
  line L1 (10.922, -4.0762) -> (-15.3535, -4.0762)
  line L2 (10.922, -1.91) -> (10.922, -4.0762)
  line L3 (-1.2117, 20.5407) -> (-1.2117, 19.8432)
  line L4 (-12.7, 7.6184) -> (-8.3633, 7.6184)
  line L5 (-17.78, 3.81) -> (-12.7, 7.6184)
  line L6 (-15.3535, -4.0762) -> (-17.78, 3.81)
  arc A1 centre (10.922, 4.318) radius 6.228 clockwise from (10.922, -1.91) to (4.6941, 4.3437)
  arc A2 centre (0, 11.43) radius 8.5 clockwise from (4.6941, 4.3437) to (-1.2117, 19.8432)
  arc A3 centre (0, 11.43) radius 9.1909 clockwise from (-8.3633, 7.6184) to (-1.2117, 20.5407)
  circle C1 centre (2.1886, -0.7383) radius 3.8635
  tangent A2 C1
  tangent A1 C1
extrude "Extrude27" cut sketch "Sketch19" profile of A1 A2 C1 against normal blind 7.366
chamfer "Chamfer1" distance 2.54
extrude "Extrude28" add of existing geometry blind 80.01
extrude "Extrude29" add of existing geometry blind 80.01
extrude "Extrude30" add of existing geometry blind 87.376
sketch "Sketch20" plane through (0, 65.024, 0) normal (0, -1, 0) x axis (1, 0, 0)
  line L1 (17.78, 10.16) -> (17.78, 3.81)
  line L2 (12.7, 25.4) -> (17.78, 10.16)
  line L3 (-12.7, 25.4) -> (12.7, 25.4)
  line L4 (-17.78, 10.16) -> (-12.7, 25.4)
  line L5 (-17.78, 3.81) -> (-17.78, 10.16)
  line L6 (-15.3535, -4.0762) -> (-17.78, 3.81)
  line L7 (-12.7, -12.7) -> (-15.3535, -4.0762)
  line L8 (-12.7, -12.623) -> (-12.7, -12.7)
  line L9 (10.922, -12.623) -> (-12.7, -12.623)
  line L10 (10.922, -12.7) -> (10.922, -12.623)
  line L11 (12.7, -12.7) -> (10.922, -12.7)
  line L12 (17.78, 3.81) -> (12.7, -12.7)
  line L13 (-1.2117, 23.5797) -> (-1.2117, 19.8432)
  line L14 (1.2883, 23.5797) -> (-1.2117, 23.5797)
  line L15 (1.2883, 19.8318) -> (1.2883, 23.5797)
  circle C1 centre (0, 0) radius 2.75
  arc A1 centre (0, 11.43) radius 8.5 clockwise from (1.2883, 19.8318) to (-1.2117, 19.8432)
  circle C2 centre (10, 2.128) radius 4.425
  circle C3 centre (10, 2.128) radius 4
  point P20 (10, 2.128)
  point P21 (0, 0)
  concentric C2 C3
  dimension "d81" diameter C2 = 8.85
  dimension "d82" distance P20 P21 = 10
  dimension "d83" diameter C3 = 8 (= "8.85 mm - 0.85 mm")
extrude "Extrude31" add sketch "Sketch20" profile of C2 C3 along normal blind 3
extrude "Extrude32" cut of existing geometry distance 82
sketch "Sketch21" plane through (0, 65.024, 0) normal (0, -1, 0) x axis (1, 0, 0)
  line L1 (-1.2117, 23.5797) -> (-1.2117, 19.8432)
  line L2 (1.2883, 23.5797) -> (-1.2117, 23.5797)
  line L3 (1.2883, 19.8318) -> (1.2883, 23.5797)
  line L4 (17.78, 10.16) -> (17.78, 3.81)
  line L5 (12.7, 25.4) -> (17.78, 10.16)
  line L6 (-12.7, 25.4) -> (12.7, 25.4)
  line L7 (-17.78, 10.16) -> (-12.7, 25.4)
  line L8 (-17.78, 3.81) -> (-17.78, 10.16)
  line L9 (-15.3535, -4.0762) -> (-17.78, 3.81)
  line L10 (-12.7, -12.7) -> (-15.3535, -4.0762)
  line L11 (-12.7, -12.623) -> (-12.7, -12.7)
  line L12 (10.922, -12.623) -> (-12.7, -12.623)
  line L13 (10.922, -12.7) -> (10.922, -12.623)
  line L14 (12.7, -12.7) -> (10.922, -12.7)
  line L15 (17.78, 3.81) -> (12.7, -12.7)
  line L16 (17.914, 2.7362) -> (14.383, 2.7362)
  line L17 (17.914, -2.2638) -> (17.914, 2.7362)
  line L18 (14.383, -2.2638) -> (17.914, -2.2638)
  line L19 (9.906, 2.7362) -> (17.914, 2.7362)
  line L20 (9.906, -2.2659) -> (9.906, 2.7362)
  line L21 (17.914, -2.2659) -> (9.906, -2.2659)
  line L22 (17.914, 2.7362) -> (17.914, -2.2659)
  arc A1 centre (0, 11.43) radius 8.5 clockwise from (1.2883, 19.8318) to (-1.2117, 19.8432)
  circle C1 centre (0, 0) radius 2.75
  circle C2 centre (10, 2.128) radius 4.425
  point P21 (14.383, 2.7362)
  point P24 (14.383, -2.2638)
  horizontal L16
  vertical L17
  horizontal L18
  coincident C2 P21
  horizontal L19
  vertical L20
  horizontal L21
  vertical L22
  dimension "d88" distance P21 P24 = 5 (= "3.8 mm + 1.2 mm")
extrude "Extrude33" cut sketch "Sketch21" profile of L15 C2 L16 L17 L19 L20 L21 L22 against normal blind 81.4
work_axis "WorkAxis1"
work_plane "WorkPlane3" RotateAngle -45
work_plane "WorkPlane4" RotateAngle 45
sketch "Sketch22" plane through (0, 53.848, 11.43) normal (-0.7071, 0, 0.7071) x axis (0, -1, 0)
  circle C1 centre (-95.79, 0) radius 2.4
  circle C2 centre (-95.79, 0) radius 1.5
extrude "Extrude34" cut sketch "Sketch22" profile of C2 against normal blind 44.45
